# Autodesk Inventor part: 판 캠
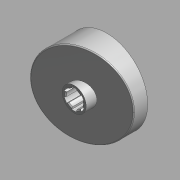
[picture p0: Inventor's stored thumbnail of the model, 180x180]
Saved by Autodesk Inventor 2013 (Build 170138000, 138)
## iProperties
Created: 2015-11
Part Number: 판 캠
Document SubType Name: 모델링
Designer: mdu
Material: 강철, 연강
Density: 7.86 g/cm^3
Mass: 682.454 g
Surface Area: 331.301 cm^2
Volume: 86.8262 cm^3
변환 표준: STEP AP214IS
파일 이름: C:\Users\SeoGD\Desktop\?쒗뿕\??stp
전처리기: Build: 253, Release: 2010 SP1 - Date: Wed 07/29/2009
전송 단위: 밀리미터
불확실성: 0.01
Author: mdu
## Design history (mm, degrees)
node "작업 평면4"
sketch "스케치1"
  geometry: C1 r 44.5 at (0, 0); 1 further point
  constraints: 1 centre point, 1 coincident
  dimensions: "d25" = 89 diameter of C1
extrude "돌출1" new body sketch "스케치1" distance "d1" = 40; taper "d2" = 0 deg
sketch "스케치2"
  geometry: L1 (-44.5, 15)-(44.5, 38.847); L2 (-44.5, 0)-(-44.5, 40) reference; L3 (-44.5, 40)-(44.5, 40) reference; L4 (44.5, 0)-(44.5, 40) reference; 1 further point
  constraints: 2 end point, 2 point on line
  dimensions: "d26" = 15 distance of L2.start L1.start; "d27" = 75 deg angle of L1 L2
extrude "돌출2" cut sketch "스케치2" stored distance "d5" = 40; taper "d6" = 0 deg
node "작업 평면1"
sketch "스케치3"
  geometry: C1 r 13 at (0, 0); 1 further point
  constraints: 1 centre point, 1 coincident
  dimensions: "d9" = 26 diameter of C1
extrude "돌출3" join sketch "스케치3" distance "d10" = 38; taper "d11" = 0 deg
hole "구멍1" diameter "d14" = 18; stored, may be unused: countersink angle "d18" = 90 deg, drill point angle "d20" = 118 deg; dims "d12" = 10, "d13" = 10, "d15" = 6, "d16" = 4, "d17" = 2, "d19" = 8
feature "쉘2" dims "d29" = 5
sketch "스케치6"
  geometry: C1 r 17.5 at (0, 0); C2 r 14 at (0, 0) reference; 1 further point
  constraints: 1 centre point, 1 coincident
  dimensions: "d28" = 35 diameter of C1
extrude "돌출4" join sketch "스케치6" stored distance "d30" = 38; taper "d31" = 0 deg
fillet "모깎기1" dims "d32" = 3
chamfer "모따기1" distance "d21" = 1; stored, may be unused: second distance "d22" = 2, angle "d23" = 45 deg
sketch "스케치7"
  geometry: L1 (-12.374, 12.374)-(-27.931, 27.931); A1 r 39.5 centre (0, 0) between (-27.931, 27.931) and (0, 39.5) reference; 2 further points
  constraints: 2 end point, 2 point on circle, 1 point on line, 1 vertical alignment, 2 other
  dimensions: "d33" = 45 deg dimension on point (0, 0) L1.start A1.end
feature "리브1" sketch "스케치7" dims "d34" = 5, "d35" = 1, "d36" = 0
fillet "모깎기2" dims "d37" = 3
sketch "스케치8"
  geometry: L1 (2.5, 10.712)-(2.5, 8.646); L2 (-2.5, 10.712)-(-2.5, 8.646); A1 r 11 centre (0, 0) between (2.5, 10.712) and (-2.5, 10.712); A2 r 9 centre (0, 0) between (2.5, 8.646) and (-2.5, 8.646) reference; 1 further point
  constraints: 4 end point, 4 point on circle, 2 parallel, 1 centre point, 1 coincident, 1 vertical
  dimensions: "d41" = 22 diameter of A1; "d42" = 5 distance between parallel lines of L1 L2
extrude "돌출5" cut sketch "스케치8" stored distance "d43" = 38; taper "d44" = 0 deg
fillet "모깎기3" dims "d48" = 1
node "솔리드1"
node "솔리드 본체"
node "곡면 본체"
pattern_circular "원형 패턴1" dims angle "d39" = 360 deg
pattern_circular "원형 패턴2" dims angle "d46" = 360 deg
node "솔리드2"
